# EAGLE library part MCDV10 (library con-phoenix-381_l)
Mini-Combicon Doppelstock-Grundgehäuse 3,81mm vertikal 2x10-polig MCDV 1,5/10-G-3,81 (ohne Gegenstecker)
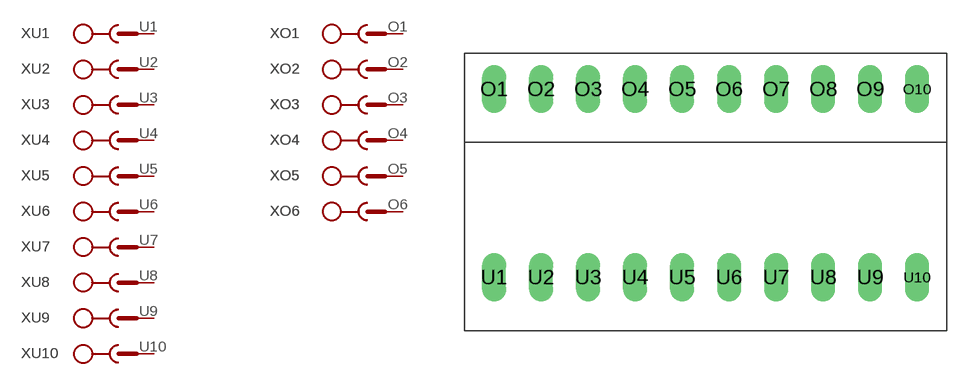
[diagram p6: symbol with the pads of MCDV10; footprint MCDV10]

Designator prefix X; gates U1=SK U2=SK U3=SK U4=SK U5=SK U6=SK U7=SK U8=SK U9=SK U10=SK O1=SK O2=SK O3=SK O4=SK O5=SK O6=SK O7=SK O8=SK O9=SK O10=SK

## MCDV101  [MCDV10]
O1  O1:1  pas
O2  O2:1  pas
O3  O3:1  pas
O4  O4:1  pas
O5  O5:1  pas
O6  O6:1  pas
O7  O7:1  pas
O8  O8:1  pas
O9  O9:1  pas
O10  O10:1  pas
U1  U1:1  pas
U2  U2:1  pas
U3  U3:1  pas
U4  U4:1  pas
U5  U5:1  pas
U6  U6:1  pas
U7  U7:1  pas
U8  U8:1  pas
U9  U9:1  pas
U10  U10:1  pas

## Footprint MCDV10 (pad centres in mm)
2x10polig 3.81 Klemme
drill 1.3 long: O1 -17.145,7.62; O2 -13.335,7.62; O3 -9.525,7.62; O4 -5.715,7.62; O5 -1.905,7.62; O6 1.905,7.62; O7 5.715,7.62; O8 9.525,7.62; O9 13.335,7.62; O10 17.145,7.62; U1 -17.145,-7.62; U2 -13.335,-7.62; U3 -9.525,-7.62; U4 -5.715,-7.62; U5 -1.905,-7.62; U6 1.905,-7.62; U7 5.715,-7.62; U8 9.525,-7.62; U9 13.335,-7.62; U10 17.145,-7.62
